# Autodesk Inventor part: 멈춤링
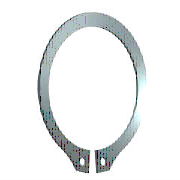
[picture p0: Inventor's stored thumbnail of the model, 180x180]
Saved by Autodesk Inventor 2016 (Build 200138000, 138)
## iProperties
IsCustomPart: 1
Created: 2012-02
Part Number: 멈춤링
Material: 강철, 연강
Description: 리테이닝 링(C형)
Document SubType Name: Modeling
Standard: KS B 1336
Designer: mduedu
Standards Organization: KS
Language: ko-KR
Size Designation: 20 x 1.2
Categories: <MemberInstance><Categories><Category DisplayName="샤프트 부품" InternalName="7f7aeb1f-a693-4053-b835-cee3144e0d98" Mnemonic="SHFT"><Category DisplayName="써클립" Inter
Density: 7.85 g/cm^3
Appearance: 노란색
Mass: 1.66335 g
Surface Area: 5.4075 cm^2
Volume: 0.211892 cm^3
Author: mduedu
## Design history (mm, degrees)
sketch "스케치1"
  geometry: L1 (-6, 0)-(6, 0) reference; L2 (0, 20.189)-(0, -80.536) reference; L3 (-48.09, 0)-(48.09, 0) reference; L4 (-0.5, -19.487)-(-0.5, -23.387); L5 (-0.5, -6.54)-(-0.5, -13.29); L6 (-2.795, 2.7)-(3.672, 2.7); L7 (0.5, -6.54)-(0.5, -13.29); L8 (0.5, -19.487)-(0.5, -23.387); C1 r 1 at (-2, -21.219); C2 r 1 at (2, -21.219); A1 r 9.5 centre (0, -10) between (0.5, -19.487) and (-0.5, -19.487); A2 r 12.025 centre (0, -9.325) between (5.071, -20.228) and (-5.071, -20.228); A3 r 13.396 centre (0, -10) between (-2.351, -23.188) and (-0.5, -23.387); A4 r 2 centre (-2, -21.219) between (-3.957, -21.631) and (-2.351, -23.188); A5 r 2 centre (-5.915, -22.042) between (-3.957, -21.631) and (-5.071, -20.228); A6 r 2 centre (5.915, -22.042) between (5.071, -20.228) and (3.957, -21.631); A7 r 2 centre (2, -21.219) between (2.351, -23.188) and (3.957, -21.631); A8 r 13.396 centre (0, -10) between (0.5, -23.387) and (2.351, -23.188)
  constraints: 16 point on circle, 12 end point, 10 centre point, 9 symmetric about line, 5 point on line, 4 tangent, 3 coincident, 2 horizontal, 1 perpendicular, 1 vertical, 5 other
  dimensions: "d0" = 19 diameter of A1 (= ND); "d1" = 3.9 distance of L4.end L4.start (= SRB2); "d6" = 0.5 distance between parallel lines of L2 L5 (= 0.25 x SD5); "d7" = 2.7 distance between parallel lines of L6 L3 (= SRB1); "d8" = 0.675 distance of A1.centre A2.centre (= 0.25 x SRB1); "d9" = 2 radius of A4 (= SD5); "d10" = 2 radius of A5 (= SD5); "d11" = 1.5 distance from line of L4 A4.centre (= 0.75 x SD5); "d12" = 2 diameter of C1 (= SD5); "d13" = 2 diameter of C2 (= SD5); "d14" = 10 distance from line of A1.centre L1 (= 0.5 x WD)
extrude "본체" new body sketch "스케치1" distance "d2" = 1.2 (= SD); taper "d3" = 0 deg
workaxis "Work Axis1"
workplane "Work Plane1"
body "Solid1"
other parameters: "SD" = 1.2 [user parameter; used in 1 equation term], "SRB1" = 2.7 [user parameter; used in 2 equation terms], "ND" = 19 [user parameter; used in 1 equation term], "SRB2" = 3.9 [user parameter; used in 1 equation term], "SD5" = 2 [user parameter; used in 6 equation terms], "d15" = 0, "d16" = 0, "d17" = 0, "d41" = 0, "d42" = 0, "SD3" = 18.5 [user parameter], "WDMAX" = 21 [user parameter]
